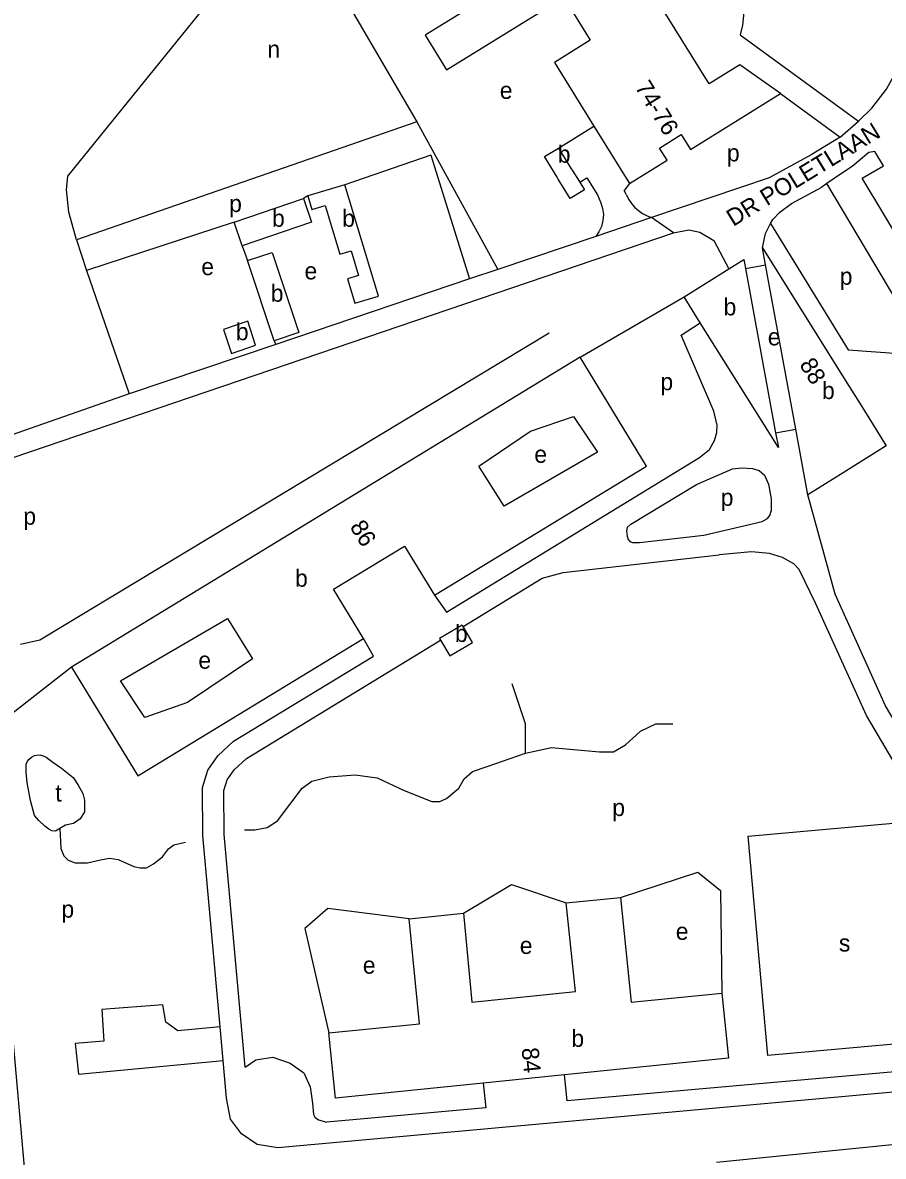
# Model space of a CAD drawing. Extents: x 158142 to 159655, y 385262 to 387204.
# Drawn here: x 158393.2 to 158594.4, y 386585.1 to 386850.2 of the extents above; entities that cross this region are included whole.
import ezdxf

# ---------------------------------------------------------------- set-up
doc = ezdxf.new("R2010")
doc.units = 0
for name, color, linetype in [('BLT_Basislijn', 7, 'Continuous'), ('BLT_Bebouwing', 7, 'Continuous'), ('BLT_Centroide', 7, 'Continuous'), ('BLT_Huisnummer', 7, 'Continuous'), ('BLT_Huisnummer_reeks', 7, 'Continuous'), ('BLT_Straatnaam_verkleind', 7, 'Continuous'), ('BLT_Vlakafsluiter', 7, 'Continuous')]:
    doc.layers.add(name, color=color, linetype=linetype)

msp = doc.modelspace()

# ---------------------------------------------------------------- linework, layer by layer
at = {"layer": 'BLT_Basislijn'}
for p, q in [((158455.35, 386878.49), (158485.3, 386827.07)), ((158560.88, 386847.42), (158588.55, 386827.21)), ((158570.34, 386833.65), (158584.26, 386823.48)), ((158584.26, 386823.48), (158588.55, 386827.21)), ((158485.3, 386827.07), (158405.76, 386799.46)), ((158485.3, 386827.07), (158504.27, 386792.52)), ((158518.46, 386820.9), (158526.73, 386826.02)), ((158488.61, 386819.23), (158468.5, 386812.33)), ((158488.61, 386819.23), (158497.67, 386790.29)), ((158523.39, 386812.93), (158525.06, 386813.95)), ((158525.06, 386813.95), (158527.56, 386809.94)), ((158584.1, 386814.66), (158581.18, 386812.61)), ((158535.04, 386812.62), (158533.75, 386810.96)), ((158581.18, 386812.61), (158580, 386811.78)), ((158459.83, 386809.7), (158458.85, 386809.1)), ((158534.35, 386809.99), (158533.75, 386810.96)), ((158442.59, 386803.54), (158408.09, 386792.27)), ((158540.21, 386804.67), (158527.15, 386800.25)), ((158568.03, 386803.25), (158568.52, 386804.21)), ((158360.27, 386738.05), (158545.3, 386801.11)), ((158405.76, 386799.46), (158408.09, 386792.27)), ((158444.48, 386798.02), (158445.71, 386794.59)), ((158527.15, 386800.25), (158504.27, 386792.52)), ((158562.12, 386792.7), (158566.84, 386793.58)), ((158408.09, 386792.27), (158418.09, 386763.39)), ((158497.67, 386790.29), (158452.34, 386774.97)), ((158504.27, 386792.52), (158497.67, 386790.29)), ((158523.53, 386771.96), (158547.79, 386786.1)), ((158452.34, 386774.97), (158418.09, 386763.39)), ((158451.97, 386775.82), (158452.34, 386774.97)), ((158418.09, 386763.39), (158356.45, 386741.94)), ((158569.2, 386754.28), (158573.92, 386755.15)), ((158496.14, 386709.01), (158514.61, 386720.27)), ((158440.03, 386607.46), (158439.32, 386615.39)), ((158440.82, 386598.65), (158440.03, 386607.46)), ((158555.4, 386583.71), (158636.14, 386591.88))]:
    msp.add_line(p, q, dxfattribs=at)
for points in [[(158588.55, 386827.21), (158591.7, 386830.27), (158595.11, 386834.66), (158597.78, 386839.54), (158599.8, 386845.67), (158600.25, 386849.45), (158600.15, 386853.26), (158599.44, 386857.59), (158598, 386861.47), (158594.4, 386868.25), (158591.12, 386873.15), (158587.7, 386877.49), (158583.18, 386881.78), (158579.53, 386884.75), (158576.62, 386886.78), (158574.2, 386888.04)], [(158405.76, 386799.46), (158404, 386805.94), (158403.45, 386811.11), (158403.75, 386814.36), (158434.32, 386852.05), (158455.35, 386878.49)], [(158558.91, 386862.97), (158559.99, 386860.98), (158560.84, 386858.83), (158561.41, 386856.57), (158561.71, 386854.24), (158561.71, 386851.91), (158561.43, 386849.62), (158560.88, 386847.42)], [(158584.26, 386823.48), (158577.52, 386819.3), (158567.71, 386813.96), (158540.21, 386804.67)], [(158590.98, 386819.85), (158587.07, 386816.63), (158584.1, 386814.66)], [(158609.67, 386780.2), (158589.44, 386813.85), (158594.37, 386816.75), (158592.35, 386820.08), (158590.98, 386819.85)], [(158568.03, 386803.25), (158586.12, 386773.69), (158597.99, 386772.83), (158602.92, 386776.03), (158581.18, 386812.61)], [(158568.52, 386804.21), (158570.21, 386805.89), (158572.88, 386807.97), (158580, 386811.78)], [(158527.56, 386809.94), (158528.36, 386808.08), (158528.76, 386806.77), (158528.92, 386805.37), (158528.82, 386803.95), (158528.48, 386802.59), (158527.9, 386801.34), (158527.15, 386800.25)], [(158534.35, 386809.99), (158534.84, 386808.96), (158535.47, 386807.97), (158536.24, 386807.07), (158537.12, 386806.27), (158538.09, 386805.59), (158539.13, 386805.06), (158540.21, 386804.67)], [(158566.1, 386797.56), (158566.84, 386800.89), (158568.03, 386803.25)], [(158545.3, 386801.11), (158548.89, 386801.77), (158551.46, 386801.26), (158554.78, 386799.29), (158558.26, 386792.65)], [(158551.4, 386748.54), (158553.73, 386750.4), (158554.94, 386752.53), (158555.48, 386754.35), (158555.49, 386756.08), (158554.75, 386759.39), (158547.13, 386777.14), (158551.57, 386780.06)], [(158516.25, 386777.61), (158397.21, 386705.81), (158392.71, 386704.81)], [(158489.45, 386716.31), (158492.24, 386712.38), (158551.4, 386748.54)], [(158535.34, 386732.9), (158550.67, 386742.24), (158559.08, 386745.85), (158561.33, 386746.11), (158563.81, 386745.99), (158565.31, 386745.52), (158566.6, 386744.41), (158567.49, 386742.25), (158568.16, 386738.82), (158568.17, 386735.98)], [(158620.27, 386651.95), (158605.13, 386673.03), (158594.88, 386690.47), (158583.1, 386716.52), (158576.75, 386739.81)], [(158535.34, 386732.9), (158534.52, 386732.12), (158534.37, 386731.38), (158534.51, 386730.1), (158534.71, 386729.33), (158535.08, 386728.91), (158535.71, 386728.64), (158537.34, 386728.66), (158552.41, 386730.38), (158566.06, 386733.58), (158567.33, 386734.29), (158567.86, 386734.95), (158568.17, 386735.98)], [(158585.85, 386698.3), (158578.62, 386714.3), (158574.66, 386722.33), (158573.45, 386723.68), (158570.78, 386725.17), (158567.78, 386726.09), (158563.55, 386726.44), (158556.02, 386725.76)], [(158514.61, 386720.27), (158519.54, 386721.6), (158556.02, 386725.76)], [(158439.32, 386615.39), (158435.32, 386660.09), (158435.23, 386671.33), (158436.46, 386675.38), (158438.83, 386678.75), (158442.46, 386682.15), (158475.2, 386702.06), (158472.88, 386706.22)], [(158445.19, 386605.95), (158440.32, 386660.33), (158440.23, 386670.61), (158441.01, 386673.16), (158442.62, 386675.45), (158445.5, 386678.15), (158490.88, 386705.8)], [(158404.59, 386699.52), (158384.48, 386683.83), (158394.81, 386568.41)], [(158617.01, 386644.4), (158616.96, 386646.73), (158616.24, 386648.98), (158600.94, 386670.3), (158590.44, 386688.17), (158585.85, 386698.3)], [(158510.69, 386679.33), (158510.69, 386686.25), (158507.64, 386695.57)], [(158510.69, 386679.33), (158516.84, 386680.69), (158528.01, 386679.65), (158531.28, 386679.65), (158534.12, 386681.28), (158537.6, 386684.5), (158541.2, 386686.19), (158545.17, 386686.19)], [(158401.87, 386661.76), (158400.85, 386661.12), (158400.04, 386661.21), (158399.27, 386661.61), (158398.34, 386662.28), (158396.96, 386663.6), (158395.96, 386664.8), (158395.02, 386668.27), (158394.21, 386672.52), (158393.97, 386674.92), (158394.02, 386676.76), (158394.33, 386677.48), (158394.64, 386677.91), (158395.23, 386678.44), (158395.94, 386678.79), (158396.45, 386678.93), (158397.24, 386678.95)], [(158397.24, 386678.95), (158398.01, 386678.77), (158398.71, 386678.4), (158400.24, 386677.23), (158402.24, 386675.84), (158404.98, 386673.68), (158406.14, 386671.85), (158407.26, 386669.91), (158407.68, 386668.4), (158407.65, 386665.67), (158406.63, 386664.02), (158405.09, 386662.92), (158403.24, 386662.5), (158401.87, 386661.76)], [(158445.08, 386661.42), (158447.43, 386661.42), (158450.31, 386661.96), (158452.78, 386663.54), (158458.51, 386671.18), (158460.78, 386672.8), (158464.83, 386673.85), (158470.93, 386674.32), (158476.09, 386673.63), (158482.36, 386670.63), (158488.82, 386668.09), (158490.7, 386668.09), (158492.25, 386668.74), (158495.11, 386671.15), (158496.42, 386673.39), (158498.36, 386675.11), (158501.77, 386676.28), (158510.69, 386679.33)], [(158401.87, 386661.76), (158402.14, 386657.03), (158402.78, 386655.32), (158403.83, 386654.32), (158405.44, 386653.7), (158408.35, 386653.7), (158411.41, 386654.45), (158413.48, 386654.8), (158415.55, 386654.53), (158419.17, 386652.84), (158420.63, 386652.53), (158422.13, 386652.53), (158423.78, 386653.46), (158425.89, 386655.08), (158427.26, 386656.98), (158428.54, 386657.94), (158431.28, 386658.54)], [(158532.92, 386645.63), (158551.04, 386651.54), (158556.31, 386647.27), (158556.65, 386623.24)], [(158496.21, 386641.91), (158507.47, 386648.65), (158520.2, 386644.34)], [(158483.5, 386640.62), (158464.53, 386643), (158459.13, 386638.36), (158464.74, 386613.93)], [(158439.32, 386615.39), (158429.43, 386614.38), (158426.69, 386616.44), (158425.93, 386620.49), (158411.7, 386619.44), (158412.2, 386612), (158405.5, 386611.43), (158406.21, 386604.28), (158440.03, 386607.46)], [(158445.19, 386605.95), (158447.72, 386607.67), (158451.69, 386608.28), (158455.71, 386606.88), (158458.9, 386604.56), (158460.42, 386601.32), (158460.9, 386597.48), (158461.21, 386594.86), (158461.52, 386594.19), (158462.32, 386593.59), (158464.25, 386593.08)], [(158605.85, 386605.61), (158520.48, 386598.05), (158519.86, 386604.13)], [(158633.64, 386603.39), (158452.87, 386587.05), (158448.01, 386587.83), (158444.32, 386590.32), (158441.8, 386593.78), (158440.82, 386598.65)], [(158500.84, 386602.2), (158501.43, 386596.37), (158464.25, 386593.08)]]:
    msp.add_lwpolyline(points, dxfattribs=at)
msp.add_lwpolyline([(158562.78, 386659.99), (158597.51, 386663.1), (158602.1, 386611.75), (158567.37, 386608.64)], close=True, dxfattribs=at)
at = {"layer": 'BLT_Bebouwing'}
for p, q in [((158526.73, 386826.02), (158535.04, 386812.62)), ((158468.5, 386812.33), (158459.83, 386809.7)), ((158451.97, 386775.82), (158445.71, 386794.59)), ((158547.79, 386786.1), (158558.26, 386792.65)), ((158551.57, 386780.06), (158547.79, 386786.1)), ((158523.53, 386771.96), (158404.59, 386699.52)), ((158521.97, 386758.13), (158527.53, 386749.75)), ((158527.53, 386749.75), (158505.73, 386737.12)), ((158505.73, 386737.12), (158499.83, 386746.53)), ((158416.02, 386696.26), (158441.06, 386710.84)), ((158441.06, 386710.84), (158446.95, 386701.42)), ((158421.71, 386687.71), (158416.02, 386696.26))]:
    msp.add_line(p, q, dxfattribs=at)
for points in [[(158491.24, 386880.18), (158493.79, 386876.08), (158476.17, 386865.15), (158481.2, 386857.05), (158498.99, 386868.08), (158505.02, 386858.34), (158487.29, 386847.34), (158492.27, 386839.2), (158519.66, 386856.18), (158525.88, 386846.15), (158517.48, 386840.94), (158526.73, 386826.02)], [(158570.34, 386833.65), (158560.86, 386840.39), (158553.66, 386835.92), (158539.56, 386858.66)], [(158535.04, 386812.62), (158543.82, 386818.06), (158542.05, 386820.91), (158547.15, 386824.07), (158549.3, 386820.6), (158570.34, 386833.65)], [(158515.18, 386818.9), (158518.46, 386820.9)], [(158518.46, 386820.9), (158521.39, 386816.08), (158521.67, 386815.71), (158523.39, 386812.93)], [(158523.39, 386812.93), (158524.5, 386811.14), (158521.16, 386809.07), (158518.33, 386813.64), (158518.11, 386814.09), (158515.18, 386818.9)], [(158459.83, 386809.7), (158460.78, 386806.56), (158463.86, 386807.5), (158467.32, 386796.07), (158469.96, 386796.87), (158471.7, 386791.1), (158469.12, 386790.32), (158470.85, 386784.6), (158476.39, 386786.28), (158468.5, 386812.33)], [(158442.59, 386803.54), (158458.85, 386809.1)], [(158458.85, 386809.1), (158460.74, 386803.58), (158444.48, 386798.02)], [(158444.48, 386798.02), (158442.59, 386803.54)], [(158445.71, 386794.59), (158451.48, 386796.51), (158457.73, 386777.74), (158451.97, 386775.82)], [(158566.1, 386797.56), (158585.85, 386765.99)], [(158566.84, 386793.58), (158566.1, 386797.56)], [(158558.26, 386792.65), (158561.73, 386794.82), (158562.12, 386792.7)], [(158562.12, 386792.7), (158569.2, 386754.28)], [(158573.92, 386755.15), (158566.84, 386793.58)], [(158569.2, 386754.28), (158569.83, 386750.88), (158551.57, 386780.06)], [(158489.45, 386716.31), (158539.03, 386746.51), (158523.53, 386771.96)], [(158585.85, 386765.99), (158588.92, 386761.1)], [(158588.92, 386761.1), (158595.06, 386751.27)], [(158499.83, 386746.53), (158511.92, 386754.66), (158521.97, 386758.13)], [(158576.75, 386739.81), (158573.92, 386755.15)], [(158595.06, 386751.27), (158583.73, 386744.18)], [(158583.73, 386744.18), (158576.75, 386739.81)], [(158472.88, 386706.22), (158465.88, 386717.7), (158482.45, 386727.79), (158489.45, 386716.31)], [(158496.14, 386709.01), (158495.94, 386709.34), (158490.63, 386706.21), (158490.88, 386705.8)], [(158490.88, 386705.8), (158493.06, 386702.1), (158498.36, 386705.23), (158496.14, 386709.01)], [(158404.59, 386699.52), (158420.09, 386674.06), (158472.88, 386706.22)], [(158446.95, 386701.42), (158431.75, 386691.18), (158421.71, 386687.71)], [(158496.21, 386641.91), (158498.22, 386621.13), (158522.4, 386623.58), (158520.2, 386644.34)], [(158520.2, 386644.34), (158532.92, 386645.63)], [(158532.92, 386645.63), (158535.4, 386621.09), (158556.65, 386623.24)], [(158483.5, 386640.62), (158496.21, 386641.91)], [(158464.74, 386613.93), (158485.94, 386616.08), (158483.5, 386640.62)], [(158556.65, 386623.24), (158558.2, 386608.01), (158519.86, 386604.13)], [(158500.84, 386602.2), (158466.28, 386598.7), (158464.74, 386613.93)], [(158519.86, 386604.13), (158500.84, 386602.2)]]:
    msp.add_lwpolyline(points, dxfattribs=at)
msp.add_lwpolyline([(158445.84, 386780.39), (158440.14, 386778.48), (158441.99, 386772.84), (158447.64, 386774.78)], close=True, dxfattribs=at)
at = {"layer": 'BLT_Vlakafsluiter'}
msp.add_line((158545.3, 386801.11), (158540.21, 386804.67), dxfattribs=at)

# ---------------------------------------------------------------- texts
at = {"layer": 'BLT_Centroide'}
for s, p in [('n', (158450.38, 386842.03)), ('e', (158504.72, 386832.41)), ('b', (158518.28, 386817.48)), ('p', (158557.81, 386817.79)), ('p', (158441.46, 386805.94)), ('b', (158451.47, 386802.49)), ('b', (158467.89, 386802.49)), ('e', (158434.95, 386791.18)), ('e', (158459.07, 386790.18)), ('p', (158584.18, 386788.93)), ('b', (158451.18, 386784.95)), ('b', (158557.03, 386781.77)), ('b', (158443.03, 386775.96)), ('e', (158567.36, 386774.75)), ('p', (158542.26, 386764.26)), ('b', (158580.03, 386762.19)), ('e', (158512.79, 386747.29)), ('p', (158556.37, 386737.21)), ('p', (158393.34, 386732.8)), ('b', (158456.86, 386718.29)), ('b', (158494.24, 386705.38)), ('e', (158434.26, 386699.12)), ('t', (158400.83, 386668.06)), ('p', (158531.01, 386664.66)), ('p', (158402.25, 386640.89)), ('e', (158545.86, 386635.7)), ('e', (158509.39, 386632.4)), ('s', (158583.98, 386632.96)), ('e', (158472.7, 386627.79)), ('b', (158521.44, 386610.66))]:
    msp.add_text(s, height=4, dxfattribs=at).set_placement(p)
at = {"layer": 'BLT_Huisnummer'}
for s, rotation, p in [('88', 301.4443, (158574.64, 386770.29)), ('86', 301.4443, (158469.54, 386732.34)), ('84', 275.7842, (158509.79, 386610.32))]:
    msp.add_text(s, height=4, rotation=rotation, dxfattribs=at).set_placement(p)
at = {"layer": 'BLT_Huisnummer_reeks'}
msp.add_text('74-76', height=4, rotation=301.4443, dxfattribs=at).set_placement((158536.2, 386835.15))
at = {"layer": 'BLT_Straatnaam_verkleind'}
msp.add_text('DR POLETLAAN', height=4, rotation=31.407, dxfattribs=at).set_placement((158559.28, 386802.45))

doc.saveas('drawing.dxf')
